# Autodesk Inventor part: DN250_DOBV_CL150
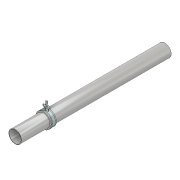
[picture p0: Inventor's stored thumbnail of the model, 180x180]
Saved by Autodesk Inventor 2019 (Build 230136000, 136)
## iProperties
Created: 2019-11
Part Number: DN250_DOBV_CL150
Material: Generic
Document SubType Name: Modeling
Designer: Admin
Density: 1 g/cm^3
Appearance: Default
Author: Admin
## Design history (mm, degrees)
derived "DN250_DOBV_CL150.iam"
body "Solid1"
node "Valve_body.ipt:1"
node "Seat.ipt:1"
body "Solid2"
node "Seat_retainer.ipt:1"
body "Solid3"
node "Shaft.ipt:1"
body "Solid4"
node "Valve_disc.ipt:1"
body "Solid5"
node "Pins.ipt:1"
body "Solid6"
node "Pins.ipt:2"
body "Solid7"
node "Outlet Pipe.ipt:1"
body "Solid8"
node "Inlet Pipe.ipt:1"
body "Solid9"
